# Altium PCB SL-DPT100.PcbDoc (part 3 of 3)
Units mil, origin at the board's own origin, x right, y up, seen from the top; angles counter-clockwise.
Board outline 2881.89 x 2169.29 mil, 4 copper layers (Top Layer, VCC, GND, Bottom Layer); 176 components, 168 nets, 589 pads, 369 vias.
Unrouted connection lines stored in the file: 2.
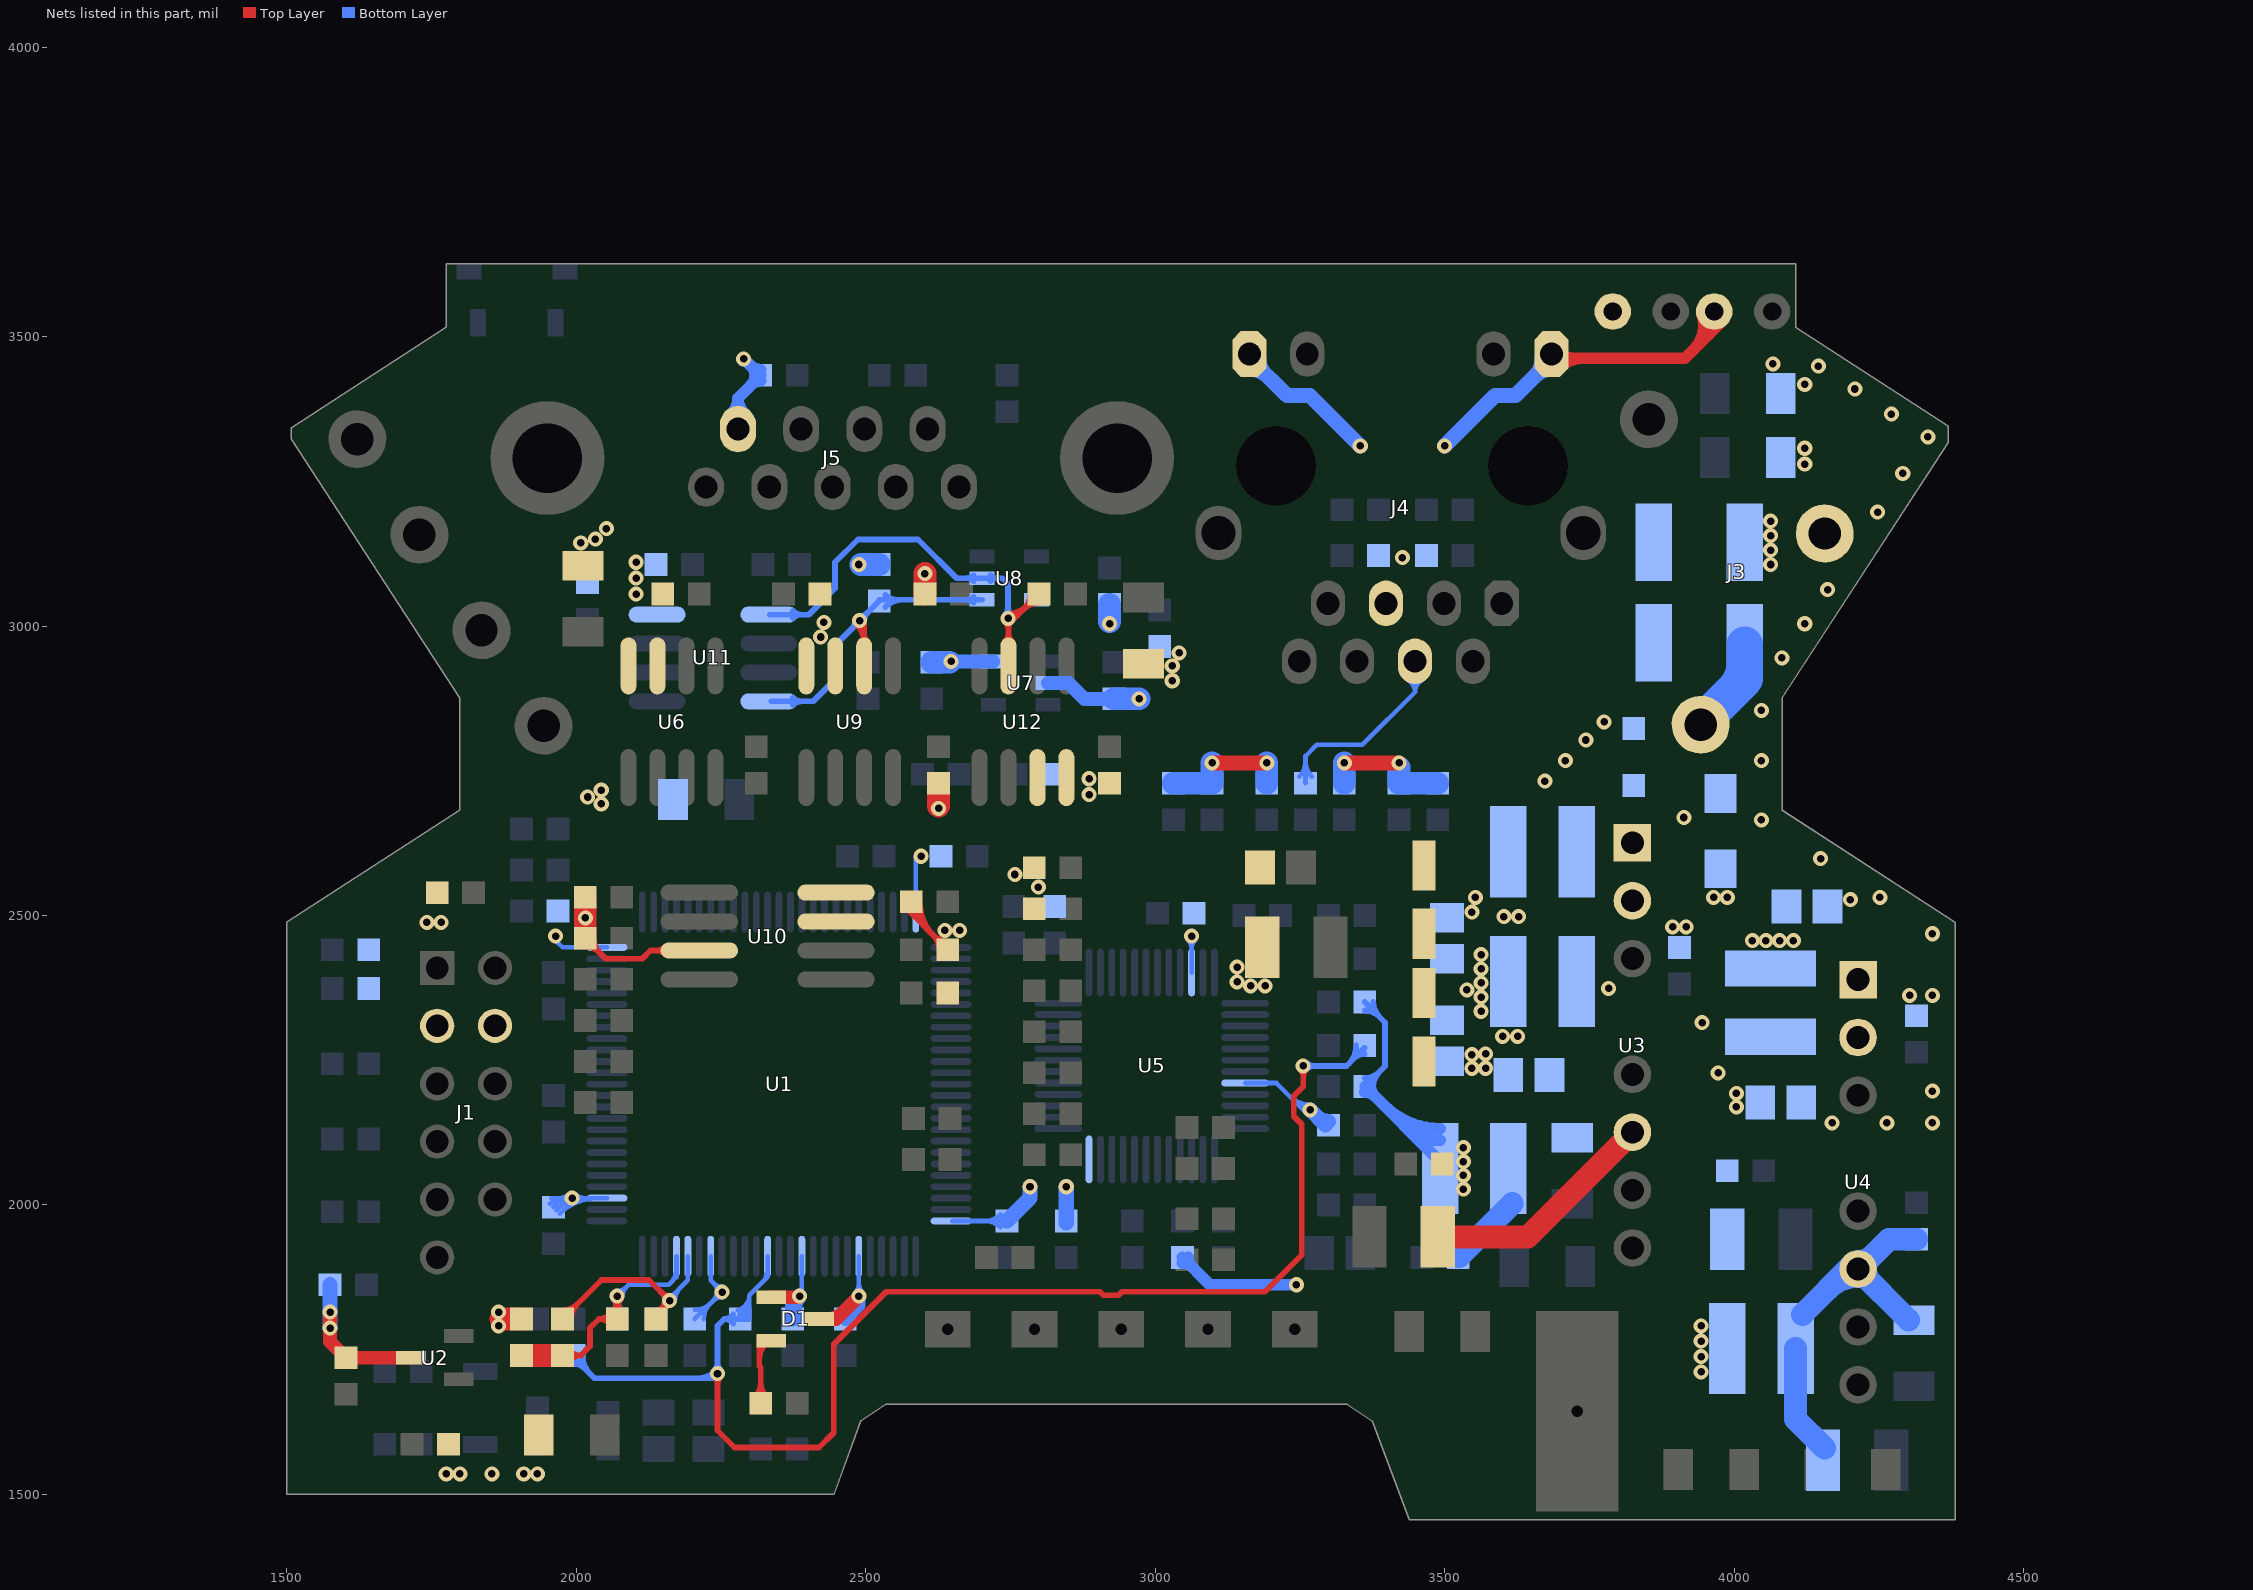
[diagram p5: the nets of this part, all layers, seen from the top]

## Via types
v1: diameter 26, hole 13, Top Layer to Bottom Layer, tented both sides, 363 vias
v2: diameter 26, hole 13, Top Layer to Bottom Layer, 4 vias
v3: diameter 27.56, hole 27.56, Top Layer to Bottom Layer, tented both sides, 2 vias

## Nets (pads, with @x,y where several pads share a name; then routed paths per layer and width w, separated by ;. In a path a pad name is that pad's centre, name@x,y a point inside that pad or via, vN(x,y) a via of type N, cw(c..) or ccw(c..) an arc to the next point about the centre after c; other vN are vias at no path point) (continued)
RST#: C48.1 R36.2 R46.1 R47.2 U1.14 | length 2981.2
  Top Layer w10: v1@2238.44,1703 cw(c2224.78,1689.35) 2244.09,1689.35 cw(c2263.41,1689.35) v1@2249.75,1703 ; v1(2244.09,1708.66) 2244.09,1610.63 2273.51,1581.21 2419.41,1581.21 2444.88,1606.69 2444.88,1759.45 2535.54,1850.11 2904.81,1850.11 2910.72,1844.2 2936.72,1844.2 2942.63,1850.11 3189.7,1850.11 3253.11,1913.52 3253.11,2139.6 3239.33,2153.38 3239.33,2188.15 3255.91,2204.72 v1@3255.91,2236.22 ; v1@3250.25,2234.5 cw(c3236.59,2220.84) 3255.91,2220.84 cw(c3275.22,2220.84) v1@3261.56,2234.5
  Bottom Layer w8: C48.1@2279.33,1818.28 ccw(c2272.2,1844.33) 2299.21,1844.33 ; C48.1@2281.44,1810.56 ccw(c2275.07,1833.85) 2299.21,1833.85 ; C48.1@2283.55,1802.85 ccw(c2277.94,1823.37) 2299.21,1823.37 ; C48.1@2299.21,1803.15 2299.21,1844.33 ; 2323.17,1868.29 ccw(c2309.57,1881.89) U1.14@2328.8,1881.89 ; U1.14@2330.71,1911.42 2330.71,1875.83 2299.21,1844.33
  Bottom Layer w10: R46.1@1933.07,1740.16 1937.01,1736.22 1996.06,1736.22 2031.49,1700.79 2242.13,1700.79 2244.09,1702.76 v1(2244.09,1708.66) 2244.09,1791.34 2255.91,1803.15 ; R46.1@1936.38,1743.47 ccw(c1953.89,1760.97) 1953.89,1736.22 ; R46.1@1943.45,1729.77 cw(c1959.02,1714.21) 1959.02,1736.22 ; R46.1@1943.45,1750.54 ccw(c1978.03,1785.12) R47.2@1978.03,1736.22 ; R46.1@1951.11,1736.22 ccw(c1951.11,1785.11) R47.2@1985.68,1750.54 ; 1970.11,1736.22 cw(c1970.11,1714.21) R47.2@1985.68,1729.77 ; 1975.25,1736.22 ccw(c1975.25,1760.97) R47.2@1992.75,1743.47 ; R47.2@1996.06,1725.47 cw(c1996.06,1699.54) 2014.4,1717.88 ; R47.2@2010.75,1740.16 ccw(c2055.72,1740.16) 2023.92,1708.36 ; 2209.71,1700.79 ccw(c2209.71,1746.98) v1@2242.37,1714.32 ; 2229.91,1700.79 ccw(c2229.91,1722.84) v1@2245.51,1707.25 ; v1@2238.44,1714.32 ccw(c2224.78,1727.98) 2244.09,1727.98 ccw(c2263.41,1727.98) v1@2249.75,1714.32 ; C48.1@2271.28,1794.96 ccw(c2255.91,1784.63) 2255.91,1803.15 ; C48.1@2271.28,1811.34 cw(c2255.91,1821.66) 2255.91,1803.15 ; C48.1@2298.03,1803.15 2255.91,1803.15 ; v1@3259.84,2240.16 3330.71,2240.16 R36.2@3362.2,2271.65 ; v1@3261.56,2234.5 cw(c3275.22,2220.84) 3275.22,2240.16 cw(c3275.22,2259.47) v1@3261.56,2245.81 ; 3334.35,2243.8 ccw(c3302.56,2275.59) R36.2@3347.52,2275.59 ; 3343.86,2253.31 cw(c3362.2,2234.96) R36.2@3362.2,2260.91
  other v1: 3255.8,2240.27
RXD: R66.1 U8.2 U11.1 U12.3 | length 1026.3
  Top Layer w10: v1@2740.41,3007.73 cw(c2725.32,2992.65) 2746.65,2992.65 ; U12.3@2740.45,2972.74 ccw(c2725.46,2987.73) 2746.65,2987.73 ccw(c2767.85,2987.73) U12.3@2752.86,2972.74 ; v1@2746.06,3011.39 ccw(c2746.06,3034.12) 2762.14,3018.04 ; v1@2746.06,3021.39 ccw(c2746.06,3068.26) 2779.21,3035.12 ; U12.3@2746.65,2923.23 2746.65,3002.56 R66.1@2799.21,3055.12 ; 2746.65,2995.5 cw(c2763.95,2995.5) v1@2751.72,3007.73 ; R66.1@2784.53,3055.12 cw(c2749.08,3055.12) 2774.14,3030.05 cw(c2799.21,3004.98) R66.1@2799.21,3040.43
  Bottom Layer w10: U11.1@2334.65,3019.68 2401.57,3019.68 2447.13,3065.24 2447.13,3110.14 2486.6,3149.61 2590.55,3149.61 2657.48,3082.68 2736.22,3082.68 2746.06,3072.83 v1@2746.06,3012.8 ; U11.1@2374.32,3013.67 cw(c2388.83,2999.16) 2388.83,3019.68 ; U11.1@2374.32,3026.09 ccw(c2389.78,3041.55) 2389.78,3019.68 ; U8.2@2686.13,3077.86 ccw(c2674.5,3066.23) 2674.5,3082.68 ccw(c2674.5,3099.12) U8.2@2686.13,3087.49 ; U8.2@2715.45,3077.86 cw(c2727.07,3066.23) 2727.07,3082.68 cw(c2727.07,3099.12) U8.2@2715.45,3087.49 ; v1@2740.41,3019.04 ccw(c2726.75,3032.7) 2746.06,3032.7 ccw(c2765.38,3032.7) v1@2751.72,3019.04
  other v1: 2746.06,3013.39
TXD: R61.1 U8.1 U9.6 U11.4 | length 809.1
  Top Layer w10: v1@2483.91,3003.6 cw(c2451.24,2970.93) U9.6@2497.44,2970.93 ; v1@2490.98,3010.67 cw(c2475.39,2995.07) 2497.44,2995.07 ; U9.6@2491.43,2972.94 ccw(c2478.42,2986.81) 2497.44,2986.81 ccw(c2516.46,2986.81) U9.6@2503.45,2972.94 ; U9.6@2497.44,2931.1 v1@2497.44,3009.65
  Bottom Layer w10: U11.4@2336.81,2870.08 2409.45,2870.08 2449.89,2910.52 2449.89,2969.57 R61.1@2523.62,3043.31 ; U11.4@2374.32,2863.67 cw(c2389.78,2848.21) 2389.78,2870.08 ; U11.4@2374.32,2876.09 ccw(c2388.83,2890.6) 2388.83,2870.08 ; v1@2481.57,3009.25 cw(c2462.25,3009.25) 2475.91,2995.6 cw(c2489.57,2981.94) v1@2489.57,3001.25 ; v1@2489.57,3017.25 ccw(c2489.57,3036.57) 2503.22,3022.91 ccw(c2516.88,3009.25) v1@2497.57,3009.25 ; R61.1@2523.62,3045.28 U8.1@2700.79,3045.28 ; R61.1@2534.01,3032.92 cw(c2563.83,3003.1) 2563.83,3045.28 ; R61.1@2534.01,3053.69 ccw(c2554.32,3074.01) 2554.32,3045.28 ; U8.1@2686.13,3040.46 ccw(c2674.5,3028.83) 2674.5,3045.28 ccw(c2674.5,3061.72) U8.1@2686.13,3050.09
  other v1: 2489.57,3009.25
V3.3: C4.1 C8.2 C27.1 C28.1 C29.1 C31.2 C32.2 C33.2 C42.1 C43.1 C44.1 C45.1 C46.1 C47.1 C55.1 C56.1 C57.2 C60.1 C64.1 C71.1 C72.1 C73.2 C74.2 C75.2 D1.1 D2.1 J1.3 J1.4 J4.4 J4.5 J4.9 J4.12 L1.2 L4.2 R15.2 R19.1 R20.2 R22.1 R23.2 R24.2 R26.1 R29.1 R31.2 R33.1 R34.2 R38.2 R48.1 R54.1 R56.2 R57.2 R58.2 R59.2 R65.2 U1.11 U1.19 U1.28 U1.50 U1.75 U1.100 U2.3 U5.22 U5.32 U5.48 U10.3 U10.7 U10.8 U12.7 U12.8 | length 5692.4
  Top Layer w10: R56.2@2015.75,2445.94 cw(c2015.75,2410.49) 2040.82,2435.56 cw(c2065.89,2460.63) R56.2@2030.43,2460.63 ; R56.2@2015.75,2460.63 2051.18,2425.2 2114.17,2425.2 2128.54,2439.57 U10.3@2212.6,2439.57 ; U10.3@2153.24,2433.36 ccw(c2138.25,2418.37) 2138.25,2439.57 ccw(c2138.25,2460.76) U10.3@2153.24,2445.77 ; C60.1@2566.93,2515.75 R58.2@2641.73,2440.94 ; C60.1@2573.43,2523.62 ccw(c2608.12,2523.62) 2583.59,2499.09 ; C60.1@2583.43,2523.62 ccw(c2642.26,2523.62) 2600.66,2482.02 ; C60.1@2593.43,2523.62 ccw(c2676.4,2523.62) 2617.73,2464.95 ; R58.2@2627.05,2440.94 ccw(c2591.59,2440.94) 2616.66,2466.01 ccw(c2641.73,2491.08) R58.2@2641.73,2455.63
  Top Layer w20: J4.9@3684.06,3462.44 3915.2,3462.44 D2.1@3982.28,3529.53 ; J4.9@3698.27,3446.23 cw(c3737.41,3407.09) 3737.41,3462.44 ; J4.9@3698.27,3473.84 ccw(c3725.79,3501.37) 3725.79,3462.44 ; 3930.36,3477.6 ccw(c3888.29,3519.66) D2.1@3945.19,3537.03 ; 3953.9,3501.15 ccw(c3924.38,3530.68) D2.1@3964.32,3542.87
  Top Layer w23.62: v1(1574.8,1814.96) 1574.8,1763.78 C55.1@1602.36,1736.22 U2.3@1714.57,1736.22 ; D1.1@2336.61,1840.55 v1@2383.86,1840.55
  Top Layer w26: v1(3098.43,2763.78) v1(3192.91,2763.78) ; v1(3326.77,2763.78) v1(3421.26,2763.78)
  Top Layer w39.37: v1@1870.08,1803.15 L1.2@1905.51,1803.15 ; R56.2@2015.75,2460.63 R59.2@2015.75,2531.5 ; v1@2625.98,2688.98 R54.1@2625.98,2728.35
  Bottom Layer w8: C46.1@1954.75,2002.02 cw(c1978.38,1978.39) C46.1@1978.38,2011.81 ; C46.1@1956.69,2011.81 U1.28@2053.15,2011.81 ; C46.1@1960.41,1996.36 cw(c1997.7,1959.07) v1@1997.7,2011.81 ; v1@1964.57,2456.69 1976.38,2444.88 U1.50@2053.15,2444.88 ; C46.1@1966.06,1990.71 cw(c2017.01,1939.76) 2017.01,2011.81 ; C46.1@1971.72,1985.05 cw(c2036.33,1920.45) U1.28@2036.33,2011.81 ; v1@1986.75,2005.45 ccw(c1971.38,1990.08) 1971.38,2011.81 ccw(c1971.38,2033.54) v1@1986.75,2018.17 ; v1@1999.47,2005.45 cw(c2014.84,1990.08) 2014.84,2011.81 cw(c2014.84,2033.54) v1@1999.47,2018.17 ; C44.1@2204.72,1803.15 2251.97,1850.39 2232.28,1870.08 U1.19@2232.28,1911.42 ; C44.1@2204.72,1818.83 ccw(c2204.72,1856.7) 2231.5,1829.93 ccw(c2258.28,1803.15) C44.1@2220.41,1803.15 ; 2235.26,1833.69 cw(c2251.97,1816.98) v1@2251.97,1840.61 ; 2237.16,1835.59 ccw(c2223.14,1849.61) v1@2242.97,1849.61 ; v1@2243.76,1849.61 ccw(c2222.03,1849.61) 2237.39,1864.97 ccw(c2252.76,1880.33) v1@2252.76,1858.61 ; v1@2389.76,1842.52 U1.11@2389.76,1911.42 ; U1.75@2586.61,2505.91 v1@2586.61,2602.36 ; U1.100@2649.61,1972.44 C45.1@2748.03,1972.44 ; C45.1@2733,1961.35 ccw(c2706.23,1934.57) 2706.23,1972.44 ccw(c2706.23,2010.31) C45.1@2733,1983.53 ; v1@3056.63,2458.2 cw(c3041.26,2442.84) 3062.99,2442.84 cw(c3084.72,2442.84) v1@3069.36,2458.2 ; U5.22@3062.99,2401.57 v1@3062.99,2464.17 ; U5.32@3155.51,2210.63 3209.65,2210.63 v1@3262.8,2157.48 ; 3232.19,2188.09 ccw(c3267.72,2223.61) v1@3267.72,2173.37 ; 3245.85,2174.43 ccw(c3267.72,2196.3) v1@3267.72,2165.37 ; C28.1@3248.75,2739.44 ccw(c3221.98,2766.21) 3259.84,2766.21 ccw(c3297.71,2766.21) C28.1@3270.93,2739.44 ; C28.1@3259.84,2728.35 3259.84,2775.59 3279.12,2794.87 3357.86,2794.87 3448.82,2885.83 ; J4.4@3436.37,2907.05 cw(c3424.51,2885.83) 3448.82,2885.83 ; J4.4@3440.28,2914.03 cw(c3432.13,2899.47) 3448.82,2899.47 cw(c3465.5,2899.45) J4.4@3457.37,2914.02 ; J4.4@3448.82,2933.07 3448.82,2885.83 ; J4.4@3461.27,2907.04 ccw(c3473.11,2885.83) 3448.82,2885.83
  Bottom Layer w10: R34.2@3362.2,2204.72 3397.24,2239.76 3397.24,2315.35 R22.1@3362.2,2350.39 ; R34.2@3362.2,2219.41 ccw(c3362.2,2254.86) 3387.27,2229.79 ccw(c3412.34,2204.72) R34.2@3376.89,2204.72 ; R22.1@3362.2,2335.71 cw(c3362.2,2300.26) 3387.27,2325.32 cw(c3412.34,2350.39) R22.1@3376.89,2350.39
  Bottom Layer w20: R23.2@3047.24,1899.76 cw(c3047.24,1876.38) 3063.78,1892.92 cw(c3080.31,1909.45) R23.2@3056.93,1909.45 ; R23.2@3047.24,1909.45 3094.49,1862.2 v1(3244.09,1862.2) ; R34.2@3362.2,2195.04 cw(c3362.2,2170.44) R34.2@3379.6,2187.84 ; R34.2@3362.71,2204.72 L4.2@3494.35,2073.09 ; R34.2@3371.89,2204.72 ccw(c3394.06,2204.72) R34.2@3378.38,2189.05 ; 3395.8,2171.63 ccw(c3492.13,2267.96) L4.2@3492.13,2131.73 ; 3429.94,2137.49 ccw(c3492.13,2199.67) L4.2@3492.13,2111.73
  Bottom Layer w26: v1(1574.8,1787.4) R48.1@1574.8,1862.2 ; C43.1@2374.02,1803.15 2374.02,1830.71 v1(2385.82,1842.52) ccw(c2408.03,1820.3) C43.1@2379.98,1806.16 ; C45.1@2744.09,1972.44 2783.86,2012.2 v1(2783.86,2031.5) ; C33.2@2846.46,1968.5 v1(2846.46,2031.5) ; J4.12@3162.81,3443.51 cw(c3162.81,3396.02) 3196.39,3429.6 ; J4.12@3169.29,3456.69 3227.75,3398.23 3267.12,3398.23 v1(3354.33,3311.02) ; J4.12@3179.33,3460.04 ccw(c3211.65,3460.04) 3188.8,3437.19 ; v1@3267.89,2164.37 C32.2@3294.47,2137.8 ; C32.2@3279.7,2152.56 ccw(c3299.21,2172.07) C32.2@3299.21,2144.48 ; v1(3500,3311.02) 3587.21,3398.23 3622.64,3398.23 J4.9@3688.98,3464.57 ; 3656.22,3431.81 cw(c3684.46,3403.58) J4.9@3684.46,3443.51 ; 3656.25,3431.84 ccw(c3628.06,3460.04) J4.9@3667.93,3460.04
  Bottom Layer w39.37: C29.1@3031.5,2728.35 R31.2@3098.43,2728.35 v1(3098.43,2763.78) ; R24.2@3192.91,2728.35 v1(3192.91,2763.78) ; R20.2@3326.77,2728.35 v1(3326.77,2763.78) ; v1@3421.26,2755.91 R15.2@3421.26,2728.35 C27.1@3488.19,2728.35
  other v1: 1775.59,1535.43 1799.21,1535.43 1854.33,1535.43 1909.45,1535.43 1933.07,1535.43 1866.14,1791.34 1866.14,1814.96 2251.97,1849.61 1993.11,2011.81 3532.48,2027.56 3532.48,2051.18 3532.48,2074.8 3532.48,2099.21 3267.72,2164.37 3164.96,2378.35 3190.16,2378.35 3141.73,2385.43 3141.73,2411.02 1964.57,2464.57 3062.99,2464.57 2636.81,2474.41 2662.4,2474.41 1742.13,2488.19 1766.54,2488.19 2015.75,2496.06 2798.23,2549.21 2757.87,2570.87 2595.67,2602.36 2625.98,2685.04 2043.31,2692.91 2019.68,2704.72 2885.83,2708.66 2043.31,2716.54 2885.83,2736.22 3427.17,3118.11
V3.3_1: C3.1 C6.2 L4.1 R3.1 U3.6 | length 541.1
  Top Layer w39.37: C3.1@3488.19,1944.88 3643.7,1944.88 U3.6@3824.41,2125.59
  Bottom Layer w39.37: C6.2@3525.06,1910.65 L4.1@3617.01,2002.6
V5.0: C17.1 C21.2 C58.1 C59.1 C61.2 C62.1 C63.1 C67.1 C68.1 C69.2 C70.2 D5.1 J5.6 L7.2 R53.2 R61.2 R63.2 R64.2 U6.7 U6.8 U7.2 U7.5 U8.5 U9.7 U9.8 U11.8 | length 671.1
  Top Layer w39.37: R64.2@2602.36,3055.12 v1(2602.36,3090.55)
  Bottom Layer w20: J5.6@2266.08,3365.39 ccw(c2242.92,3393.58) 2279.41,3393.58 ; J5.6@2279.41,3340.16 2279.41,3393.58 ; v1(2289.37,3461.61) R63.2@2314.96,3436.02 ; J5.6@2292.74,3365.39 cw(c2315.89,3393.58) 2279.41,3393.58 ; R63.2@2300.68,3450.3 ccw(c2318.9,3468.51) R63.2@2318.9,3442.76 ; R63.2@2303.06,3447.92 cw(c2288.21,3433.07) 2309.21,3433.07 cw(c2285.83,3433.07) 2302.36,3416.54 cw(c2318.9,3400) R63.2@2318.9,3423.39 ; R63.2@2318.9,3433.07 2279.41,3393.58
  Bottom Layer w23.62: v1@2648.72,2938.88 U7.5@2720.47,2938.88 ; U7.2@2814.96,2901.48 2850.49,2901.48 2877.95,2874.02 R53.2@2933.07,2874.02 ; 2909.17,2874.02 ccw(c2909.17,2894.37) R53.2@2923.57,2879.98
  Bottom Layer w39.37: v1@2492.13,3106.3 R61.2@2523.62,3106.3 ; C62.1@2614.17,2937.4 v1@2645.28,2937.4 ; v1@2921.26,3007.87 C61.2@2921.26,3037.4 ; R53.2@2929.13,2874.41 v1@2972.05,2874.41
  other v1: 3942.91,1711.61 3942.91,1738.19 3942.91,1764.76 3942.91,1791.34 2972.44,2874.02 3029.53,2905.51 3029.53,2931.1 2647.64,2938.98 3041.34,2953.74 2422.05,2981.1 2921.26,3003.94 2427.95,3006.3 2103.54,3055.12 2103.54,3082.68 2488.19,3106.3 2103.54,3110.24 2007.87,3143.7 2033.07,3150.2 2052.17,3168.31
V5.0_1: C16.1 C19.2 L7.1 R5.1 U4.6 | length 675.8
  Bottom Layer w39.37: L7.1@4106.3,1751.97 4106.3,1629.92 C16.1@4156.5,1579.72 ; L7.1@4118.11,1811.02 U4.6@4206.89,1899.8 ; 4162.09,1855 cw(c4214.17,1802.91) U4.6@4214.17,1876.57 ; U4.6@4212.6,1889.76 R5.1@4301.18,1801.18 ; U4.6@4214.17,1902.17 ccw(c4214.17,1937.81) 4239.38,1912.6 ; U4.6@4216.54,1889.76 4267.72,1940.94 C19.2@4314.96,1940.94 ; U4.6@4226.97,1889.37 ccw(c4260.71,1889.37) 4236.85,1865.51
V24+: F3.1 J3.3 | length 221.5
  Bottom Layer w62.99: J3.3@3940.94,2830.71 4018.82,2908.58 F3.1@4018.82,2967.44 ; 3999.09,2888.85 ccw(c3951.84,2936.1) F3.1@4018.66,2936.1
V24+1: D3.1 F3.2 R4.1
V24+2: D3.2 D4.2 L5.2
V24+3: C9.2 C11.1 C22.2 C65.1 C66.2 L3.1 L5.1 L6.1
  other v1: 3600.39,2291.34 3625.98,2291.34 3562.99,2334.65 3562.99,2359.05 3538.39,2371.65 3562.99,2383.46 3562.99,2407.87 3562.99,2432.28 4031.5,2456.69 4055.12,2456.69 4078.74,2456.69 4102.36,2456.69 3602.36,2498.03 3627.95,2498.03
V24+4: C10.2 L3.2 U3.2
V24+5: C23.2 L6.2 U4.2
V24-: C9.1 C10.1 C11.2 C12.2 C22.1 C23.1 C24.2 C26.1 C65.2 C66.1 D4.1 J3.1 R4.2 R71.1 U3.1 U4.1
  other v1: 4169.29,2141.73 4263.78,2141.73 4342.52,2141.73 4003.94,2169.29 4003.94,2192.91 4342.52,2196.85 3972.44,2228.35 3547.24,2236.22 3570.87,2236.22 3547.24,2259.84 3570.87,2260.83 3944.88,2314.96 4303.15,2362.2 4342.52,2362.2 3783.46,2374.02 4342.52,2468.5 3893.7,2480.32 3917.32,2480.32 3547.24,2505.91 4200.79,2527.56 3553.15,2531.5 3964.57,2531.5 3988.19,2531.5 4251.97,2531.5 4149.61,2598.43 4047.24,2665.35 3913.39,2669.29 3673.23,2732.28 3708.66,2767.72 4047.24,2767.72 3744.09,2803.15 3775.59,2834.65 4047.24,2854.33 4082.68,2944.88 4122.05,3003.94 4161.42,3062.99 4062.99,3106.3 4062.99,3131.23 4062.99,3156.17 4062.99,3181.1 4248.03,3196.85 4291.34,3263.78 4122.05,3279.53 4122.05,3307.09 4334.65,3326.77 4271.65,3366.14 4208.66,3409.45 4122.05,3417.32 4145.67,3448.82 4066.93,3452.76
V_BAT: C1.1 D1.2 | length 202.2
  Top Layer w10: C1.1@2308.51,1667.86 ccw(c2283.45,1692.93) 2318.9,1692.93 ccw(c2354.35,1692.93) C1.1@2329.28,1667.86 ; 2316.02,1732.86 cw(c2355.72,1732.86) D1.2@2327.65,1760.93 ; D1.2@2316.02,1771.65 2316.02,1721.69 2318.9,1718.82 C1.1@2318.9,1657.48
VBAT: C2.1 D1.3 U1.6 | length 311.7
  Top Layer w23.62: D1.3@2419.29,1803.15 2449.21,1803.15 v1@2488.19,1842.13 ; D1.3@2433.07,1803.15 ccw(c2433.07,1842.12) 2460.63,1814.56
  Bottom Layer w8: v1@2481.83,1848.88 ccw(c2466.46,1864.25) 2488.19,1864.25 ccw(c2509.92,1864.25) v1@2494.55,1848.88 ; v1(2488.19,1842.52) U1.6@2488.19,1911.42
  Bottom Layer w23.62: C2.1@2462.84,1810.83 ccw(c2455.71,1842.52) v1(2488.19,1842.52) 2488.19,1826.77 C2.1@2464.57,1803.15
VDDA: C40.1 C41.1 L1.1 R1.1 U1.22 | length 754.4
  Top Layer w10: R1.1@1976.38,1740.16 2007.87,1740.16 ; R1.1@1987.63,1730.72 cw(c2007.87,1713.74) 2007.87,1740.16 ; R1.1@1987.63,1749.6 ccw(c2007.87,1766.58) 2007.87,1740.16 ; C41.1@2059.62,1793.71 ccw(c2039.37,1776.72) 2039.37,1803.15 ; C41.1@2059.62,1812.59 cw(c2039.37,1829.58) 2039.37,1803.15 ; C41.1@2060.48,1813.53 ccw(c2035.41,1838.6) 2070.87,1838.6 ccw(c2106.32,1838.6) C41.1@2081.25,1813.53 ; v1@2065.21,1836.86 cw(c2051.55,1823.21) 2070.87,1823.21 cw(c2090.18,1823.21) v1@2076.52,1836.86 ; v1(2070.87,1842.52) C41.1@2070.87,1803.15 2039.37,1803.15 ; 2007.87,1740.16 2023.62,1755.91 2023.62,1787.4 2039.37,1803.15
  Top Layer w39.37: L1.1@1905.51,1740.16 R1.1@1976.38,1740.16
  Bottom Layer w8: v1(2070.87,1842.52) 2090.55,1862.2 2159.81,1862.2 2173.23,1875.63 U1.22@2173.23,1911.42 ; v1@2070.87,1851.52 ccw(c2070.87,1873.25) 2086.23,1857.88 ccw(c2101.59,1842.52) v1@2079.87,1842.52 ; 2165.55,1867.95 ccw(c2151.6,1881.89) U1.22@2171.32,1881.89
  Bottom Layer w10: C40.1@2060.48,1813.53 ccw(c2035.41,1838.6) 2070.87,1838.6 ccw(c2106.32,1838.6) C40.1@2081.25,1813.53 ; v1@2065.21,1836.86 cw(c2051.55,1823.21) 2070.87,1823.21 cw(c2090.18,1823.21) v1@2076.52,1836.86 ; C40.1@2070.87,1803.15 v1(2070.87,1842.52)
VREF+: C38.1 C39.1 R1.2 U1.21 | length 701.3
  Top Layer w10: R1.2@1976.38,1803.15 2043.59,1870.36 2125.7,1870.36 v1(2161.42,1834.65) ; R1.2@1976.38,1817.83 ccw(c1976.38,1853.29) 2001.45,1828.22 ccw(c2026.52,1803.15) R1.2@1991.06,1803.15 ; C39.1@2133.86,1807.09 v1(2161.42,1834.65) ; C39.1@2137.8,1817.83 ccw(c2137.8,1834.28) C39.1@2149.42,1822.65 ; C39.1@2142.41,1803.96 cw(c2161.54,1807.3) C39.1@2147.81,1821.04 ; C39.1@2152.26,1805.68 cw(c2184.71,1811.35) v1(2161.42,1834.65) ; v1@2161.42,1826.65 ccw(c2161.42,1807.33) 2147.76,1820.99 ccw(c2134.1,1834.65) 2153.42,1834.65 ccw(c2134.1,1834.65) 2147.76,1848.3 ccw(c2161.42,1861.96) v1@2161.42,1842.65
  Bottom Layer w8: v1@2159.45,1836.61 2192.91,1870.08 U1.21@2192.91,1911.42 ; v1@2161.42,1843.65 ccw(c2161.42,1855.87) 2170.06,1847.23 ; v1@2170.42,1834.65 cw(c2201.65,1834.65) 2179.57,1856.73
  Bottom Layer w10: C38.1@2133.86,1807.09 v1(2161.42,1834.65) ccw(c2184.71,1811.35) C38.1@2152.26,1805.68 ; C38.1@2137.8,1817.83 ccw(c2137.8,1834.28) C38.1@2149.42,1822.65 ; C38.1@2142.41,1803.96 cw(c2161.54,1807.3) C38.1@2147.81,1821.04 ; v1@2153.42,1834.65 cw(c2134.1,1834.65) 2147.76,1820.99 cw(c2161.42,1807.33) v1@2161.42,1826.65
pads on no net: J4.7 SW2.3 SW2.4 Temp1.1 Temp1.2 Temp1.3 Temp1.4 Temp1.5 Temp2.1 Temp2.2 Temp2.3 Temp2.4 U3.5 U5.8 U5.9 U5.10 U5.11 U5.12 U6.1 U6.4 U9.1 U9.4
copper on no net:
  other v3: 1864.17,3574.8 1931.1,3574.8

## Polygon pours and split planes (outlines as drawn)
V24- on Bottom Layer "V24" (solid, remove dead copper, pour order 1003): 4358.27,2129.92 4019.68,2129.92 3960.63,2188.98 3960.63,2279.53 3877.95,2362.2 3771.65,2362.2 3633.86,2224.41 3523.62,2224.41 3503.94,2244.09 3503.94,2496.06 3618.11,2610.24 3618.11,2696.85 3870.08,2948.82 3870.08,3244.09 4031.5,3244.09 4035.43,3248.03 4035.43,3464.57 4145.67,3464.57 4346.46,3334.65 4346.46,3318.9 4307.09,3263.78 4059.06,2881.89 4059.06,2673.23 4358.27,2476.38
GNDD on Bottom Layer "GNDD" (solid, remove dead copper, pour order 1004): 3004.92,2851.38 2050.2,2851.38 1948.82,2952.76 1948.82,3102.36 2027.56,3181.1 2248.03,3181.1 2283.46,3216.54 2283.46,3263.78 2248.03,3299.21 2224.41,3299.21 2192.91,3330.71 2192.91,3464.57 2241.14,3512.8 2687.01,3512.8 2795.28,3404.53 2795.28,3224.41 2870.08,3149.61 2976.38,3149.61 3064.96,3061.02 3064.96,2911.42
GNDD on Bottom Layer "GNDD" (solid, remove dead copper, pour order 1006): 4362.2,1476.38 4362.2,2086.61 3960.63,2086.61 3960.63,1874.02 3838.58,1751.97 3838.58,1476.38
GND on Bottom Layer "GND" (solid, remove dead copper, pour order 1001): 1523.62,1523.62 1523.62,2476.38 1830.71,2677.17 1925.2,2677.17 2059.06,2811.02 3023.62,2811.02 3106.3,2893.7 3106.3,3059.06 3314.96,3267.72 3314.96,3314.96 3326.77,3326.77 3527.56,3326.77 3539.37,3314.96 3539.37,3259.84 3759.84,3039.37 3759.84,2970.24 3527.72,2738.12 3527.7,2662.55 3401.57,2536.42 3401.57,2204.72 3488.19,2118.11 3807.09,2118.11 3858.27,2066.93 3858.27,1917.32 3799.21,1858.27 3488.19,1858.27 3464.57,1834.65 3464.57,1746.06 3370.08,1746.06 3370.08,1830.71 3330.71,1870.08 2500,1870.08 2500,1712.6 2429.13,1523.62
GNDD on Top Layer "GNDD" (solid, remove dead copper, pour order 1002): 3004.92,2851.38 2050.2,2851.38 1948.82,2952.76 1948.82,3102.36 2027.56,3181.1 2248.03,3181.1 2283.46,3216.54 2283.46,3263.78 2248.03,3299.21 2224.41,3299.21 2192.91,3330.71 2192.91,3464.57 2241.14,3512.8 2687.01,3512.8 2795.28,3404.53 2795.28,3224.41 2870.08,3149.61 2976.38,3149.61 3064.96,3061.02 3064.96,2911.42
GNDD on Top Layer "GNDD" (solid, remove dead copper, pour order 1007): 4362.2,1476.38 4362.2,2086.61 3960.63,2086.61 3960.63,1874.02 3838.58,1751.97 3838.58,1476.38
V24- on Top Layer "V24" (solid, remove dead copper, pour order 1005): 4358.27,2129.92 4019.68,2129.92 3960.63,2188.98 3960.63,2279.53 3877.95,2362.2 3771.65,2362.2 3633.86,2224.41 3503.94,2224.41 3484.25,2204.72 3444.88,2204.72 3444.88,2629.92 3551.18,2629.92 3618.11,2696.85 3870.08,2948.82 3870.08,3244.09 4031.5,3244.09 4035.43,3248.03 4035.43,3464.57 4145.67,3464.57 4346.46,3334.65 4346.46,3318.9 4307.09,3263.78 4059.06,2881.89 4059.06,2673.23 4358.27,2476.38
GND on Top Layer "GND" (solid, remove dead copper, pour order 1000): 1523.62,1523.62 1523.62,2476.38 1801.9,2657.48 1905.51,2657.48 2059.06,2811.02 3023.62,2811.02 3106.3,2893.7 3106.3,3059.06 3314.96,3267.72 3314.96,3314.96 3326.77,3326.77 3527.56,3326.77 3539.37,3314.96 3539.37,3259.84 3759.84,3039.37 3759.84,2970.47 3521.65,2732.28 3389.76,2732.28 3330.71,2673.23 3330.71,2169.29 3397.64,2102.36 3822.83,2102.36 3858.27,2066.93 3858.27,1917.32 3799.21,1858.27 3488.19,1858.27 3464.57,1834.65 3464.57,1746.06 3370.08,1746.06 3370.08,1830.71 3330.71,1870.08 2500,1870.08 2500,1712.6 2429.13,1523.62
V3.3 on VCC (split plane): 3539.43,3314.9 3539,3260.22 3769.59,3029.62 3769.59,2990.48 3523.41,2744.3 3520.95,2741.3 3519.13,2737.88 3518,2734.17 3517.82,2732.28 3389.76,2732.28 3330.71,2673.23 3330.71,2169.29 3397.64,2102.36 3452.76,2102.36 3469.45,2119.09 3495.1,2119.09 3496.06,2119 3827.44,2119 3885.73,2060.7 3885.73,1931.42 3808.64,1854.33 3488.19,1854.33 3488.19,1736.22 3342.52,1736.22 3342.52,1795.28 3303.15,1834.65 2566.93,1834.65 2519.68,1787.4 2519.68,1669.71 2480.39,1643.49 2480.05,1643.21 2479.67,1642.99 2478.53,1641.96 2477.34,1640.99 2477.06,1640.65 2476.74,1640.36 2475.81,1639.13 2474.84,1637.95 2474.63,1637.56 2474.37,1637.21 2473.7,1635.83 2472.98,1634.47 2472.85,1634.05 2472.66,1633.66 2431.22,1520.1 1520.1,1520.1 1520.1,2477.27 1809.58,2665.12 1809.67,2665.19 1809.77,2665.24 1811.21,2666.42 1812.66,2667.58 1812.73,2667.66 1812.82,2667.74 1814,2669.17 1815.2,2670.59 1815.26,2670.69 1815.33,2670.77 1816.21,2672.41 1817.11,2674.04 1817.14,2674.15 1817.19,2674.24 1817.74,2676.02 1818.3,2677.79 1818.31,2677.9 1818.34,2678.01 1818.53,2679.86 1818.66,2681.01 1917.32,2681.01 1921.18,2681.39 1924.89,2682.51 1928.31,2684.34 1931.31,2686.8 2056.42,2811.91 3012.8,2811.91 3016.65,2812.29 3020.36,2813.42 3023.78,2815.25 3026.78,2817.71 3098.63,2889.56 3101.09,2892.55 3102.92,2895.97 3104.05,2899.68 3104.43,2903.54 3104.23,2905.54 3104.23,3056.98 3314.96,3267.72 3314.96,3314.96 3346.46,3346.46 3507.87,3346.46
V5.0 on VCC (split plane): 3925.2,3527.56 3768.9,3371.26 3768.9,3363.17 3768.8,3362.2 3768.8,3343.7 3769.18,3339.84 3770.31,3336.13 3772.14,3332.71 3774.6,3329.71 3828.64,3275.66 3828.64,2965.87 3582.47,2719.7 3580.01,2716.7 3578.18,2713.28 3577.06,2709.57 3576.68,2705.71 3576.68,2629.85 3467.31,2520.48 3464.85,2517.49 3463.02,2514.07 3461.9,2510.35 3461.52,2506.5 3461.52,2235.24 3461.9,2231.38 3463.02,2227.67 3464.85,2224.25 3467.31,2221.25 3504.71,2183.85 3507.71,2181.39 3511.13,2179.56 3514.84,2178.43 3518.7,2178.05 3683.07,2178.05 3686.93,2178.43 3690.64,2179.56 3694.06,2181.39 3697.06,2183.85 3799.53,2286.32 3851.06,2286.32 3885.73,2251.65 3885.73,2213.58 3886.11,2209.72 3887.24,2206.01 3889.07,2202.59 3891.53,2199.6 3998.81,2092.31 4001.81,2089.85 4005.23,2088.02 4008.94,2086.9 4012.8,2086.52 4361.77,2086.52 4361.74,1714.49 4361.79,1476.79 3964.57,1476.79 3964.57,1586.61 3937.01,1586.61 3838.58,1685.04 3838.58,1828.33 3919.5,1909.24 3921.96,1912.24 3923.79,1915.66 3924.91,1919.37 3925.29,1923.23 3925.29,2068.9 3924.91,2072.76 3923.79,2076.47 3921.96,2079.89 3919.5,2082.88 3849.62,2152.77 3846.62,2155.23 3843.2,2157.05 3839.49,2158.18 3835.63,2158.56 3504.26,2158.56 3442.02,2220.79 3442.02,2522.71 3551.39,2632.08 3553.85,2635.07 3555.68,2638.49 3556.8,2642.2 3557.18,2646.06 3557.18,2722.12 3803.36,2968.3 3805.82,2971.29 3807.64,2974.71 3808.77,2978.42 3809.15,2982.28 3809.15,3259.45 3808.77,3263.31 3807.64,3267.02 3805.82,3270.44 3803.36,3273.44 3749.77,3327.02 3750.1,3330.32 3750.1,3476.77 3749.72,3480.63 3748.59,3484.34 3746.76,3487.76 3744.3,3490.76 3685.64,3549.42 3682.64,3551.88 3679.22,3553.71 3675.51,3554.83 3671.65,3555.21 2889.76,3555.21 2885.9,3554.83 2882.19,3553.71 2878.77,3551.88 2875.78,3549.42 2800.97,3474.62 2798.51,3471.62 2796.69,3468.2 2795.72,3465.01 2795.28,3464.57 2795.28,3461.6 2795.18,3460.63 2795.18,3232.28 2795.28,3231.32 2795.28,3224.41 2799.08,3220.6 2800.97,3218.3 2863.97,3155.3 2866.27,3153.41 2870.08,3149.61 2876.99,3149.61 2877.95,3149.51 2976.06,3149.51 3064.67,3060.9 3064.67,2911.54 3004.6,2851.47 2050.1,2851.47 1948.82,2952.76 1948.82,3102.36 2027.56,3181.1 2248.03,3181.1 2283.46,3216.54 2283.46,3263.78 2248.03,3299.21 2224.41,3299.21 2192.91,3330.71 2192.91,3472.44 2240.16,3519.68 2767.72,3519.68 2834.65,3586.61 3925.2,3586.61
V24+3 on VCC (split plane): 4142.62,3468.5 4349.98,3334.15 4349.98,3322.76 4065.95,2886.88 4065.09,2885.22 4064.21,2883.56 4064.18,2883.47 4064.14,2883.39 4063.61,2881.58 4063.07,2879.78 4063.06,2879.69 4063.04,2879.6 4062.87,2877.73 4062.7,2875.86 4063.15,2681.93 4063.16,2681.82 4063.15,2681.71 4063.36,2679.86 4063.55,2678.01 4063.58,2677.91 4063.59,2677.79 4064.16,2676.01 4064.7,2674.24 4064.75,2674.15 4064.78,2674.04 4065.69,2672.41 4066.56,2670.77 4066.63,2670.69 4066.69,2670.59 4067.88,2669.17 4069.07,2667.74 4069.16,2667.66 4069.23,2667.58 4070.68,2666.42 4072.12,2665.24 4072.22,2665.19 4072.31,2665.12 4361.79,2477.27 4361.77,2126.08 4020.99,2126.08 3925.29,2221.78 3925.29,2259.84 3924.91,2263.7 3923.79,2267.41 3921.96,2270.83 3919.5,2273.83 3873.24,2320.09 3870.24,2322.55 3866.82,2324.38 3863.11,2325.5 3859.25,2325.88 3791.34,2325.88 3787.48,2325.5 3783.77,2324.38 3780.35,2322.55 3777.35,2320.09 3674.88,2217.61 3526.89,2217.61 3501.08,2243.43 3501.08,2498.3 3610.44,2607.67 3612.9,2610.66 3614.73,2614.08 3615.86,2617.79 3616.24,2621.65 3616.24,2697.52 3862.41,2943.69 3864.87,2946.69 3866.7,2950.11 3867.83,2953.82 3868.21,2957.68 3868.21,3248.03 4027.56,3248.03 4027.56,3468.5
GND on GND (split plane): 3539.43,3314.9 3539,3260.22 3769.59,3029.62 3769.59,2990.48 3523.41,2744.3 3520.95,2741.3 3519.13,2737.88 3518,2734.17 3517.62,2730.31 3517.62,2654.26 3408.26,2544.89 3405.8,2541.89 3403.97,2538.47 3402.84,2534.76 3402.46,2530.91 3402.46,2212.6 3402.84,2208.74 3403.97,2205.03 3405.8,2201.61 3408.26,2198.61 3482.08,2124.79 3485.07,2122.33 3488.49,2120.5 3492.2,2119.38 3496.06,2119 3827.44,2119 3885.73,2060.7 3885.73,1931.42 3808.64,1854.33 3488.19,1854.33 3488.19,1736.22 3342.52,1736.22 3342.52,1795.28 3303.15,1834.65 2566.93,1834.65 2519.68,1787.4 2519.68,1669.71 2480.39,1643.49 2480.05,1643.21 2479.67,1642.99 2478.53,1641.96 2477.34,1640.99 2477.06,1640.65 2476.74,1640.36 2475.81,1639.13 2474.84,1637.95 2474.63,1637.56 2474.37,1637.21 2473.7,1635.83 2472.98,1634.47 2472.85,1634.05 2472.66,1633.66 2431.22,1520.1 1520.1,1520.1 1520.1,2477.27 1809.58,2665.12 1809.67,2665.19 1809.77,2665.24 1811.21,2666.42 1812.66,2667.58 1812.73,2667.66 1812.82,2667.74 1814,2669.17 1815.2,2670.59 1815.26,2670.69 1815.33,2670.77 1816.21,2672.41 1817.11,2674.04 1817.14,2674.15 1817.19,2674.24 1817.74,2676.02 1818.3,2677.79 1818.31,2677.9 1818.34,2678.01 1818.53,2679.86 1818.66,2681.01 1917.32,2681.01 1921.18,2681.39 1924.89,2682.51 1928.31,2684.34 1931.31,2686.8 2056.42,2811.91 3012.8,2811.91 3016.65,2812.29 3020.36,2813.42 3023.78,2815.25 3026.78,2817.71 3098.63,2889.56 3101.09,2892.55 3102.92,2895.97 3104.05,2899.68 3104.43,2903.54 3104.23,2905.54 3104.23,3056.98 3314.96,3267.72 3314.96,3314.96 3346.46,3346.46 3507.87,3346.46
GNDD on GND (split plane): 3925.2,3527.56 3768.9,3371.26 3768.9,3363.17 3768.8,3362.2 3768.8,3343.7 3769.18,3339.84 3770.31,3336.13 3772.14,3332.71 3774.6,3329.71 3828.64,3275.66 3828.64,2965.87 3582.47,2719.7 3580.01,2716.7 3578.18,2713.28 3577.06,2709.57 3576.68,2705.71 3576.68,2629.85 3467.31,2520.48 3464.85,2517.49 3463.02,2514.07 3461.9,2510.35 3461.52,2506.5 3461.52,2235.24 3461.9,2231.38 3463.02,2227.67 3464.85,2224.25 3467.31,2221.25 3504.71,2183.85 3507.71,2181.39 3511.13,2179.56 3514.84,2178.43 3518.7,2178.05 3683.07,2178.05 3686.93,2178.43 3690.64,2179.56 3694.06,2181.39 3697.06,2183.85 3799.53,2286.32 3851.06,2286.32 3885.73,2251.65 3885.73,2213.58 3886.11,2209.72 3887.24,2206.01 3889.07,2202.59 3891.53,2199.6 3998.81,2092.31 4001.81,2089.85 4005.23,2088.02 4008.94,2086.9 4012.8,2086.52 4361.77,2086.52 4361.74,1714.49 4361.79,1476.79 3964.57,1476.79 3964.57,1586.61 3937.01,1586.61 3838.58,1685.04 3838.58,1828.33 3919.5,1909.24 3921.96,1912.24 3923.79,1915.66 3924.91,1919.37 3925.29,1923.23 3925.29,2068.9 3924.91,2072.76 3923.79,2076.47 3921.96,2079.89 3919.5,2082.88 3849.62,2152.77 3846.62,2155.23 3843.2,2157.05 3839.49,2158.18 3835.63,2158.56 3504.26,2158.56 3442.02,2220.79 3442.02,2522.71 3551.39,2632.08 3553.85,2635.07 3555.68,2638.49 3556.8,2642.2 3557.18,2646.06 3557.18,2722.12 3803.36,2968.3 3805.82,2971.29 3807.64,2974.71 3808.77,2978.42 3809.15,2982.28 3809.15,3259.45 3808.77,3263.31 3807.64,3267.02 3805.82,3270.44 3803.36,3273.44 3749.77,3327.02 3750.1,3330.32 3750.1,3476.77 3749.72,3480.63 3748.59,3484.34 3746.76,3487.76 3744.3,3490.76 3685.64,3549.42 3682.64,3551.88 3679.22,3553.71 3675.51,3554.83 3671.65,3555.21 2889.76,3555.21 2885.9,3554.83 2882.19,3553.71 2878.77,3551.88 2875.78,3549.42 2800.97,3474.62 2798.51,3471.62 2796.69,3468.2 2795.72,3465.01 2795.28,3464.57 2795.28,3461.6 2795.18,3460.63 2795.18,3232.28 2795.28,3231.32 2795.28,3224.41 2799.08,3220.6 2800.97,3218.3 2863.97,3155.3 2866.27,3153.41 2870.08,3149.61 2876.99,3149.61 2877.95,3149.51 2976.06,3149.51 3064.67,3060.9 3064.67,2942.62 3047.24,2925.2 3047.24,2894.12 3004.6,2851.47 2050.1,2851.47 1948.82,2952.76 1948.82,3102.36 2027.56,3181.1 2248.03,3181.1 2283.46,3216.54 2283.46,3263.78 2248.03,3299.21 2224.41,3299.21 2192.91,3330.71 2192.91,3472.44 2240.16,3519.68 2767.72,3519.68 2834.65,3586.61 3925.2,3586.61
V24- on GND (split plane): 4142.62,3468.5 4349.98,3334.15 4349.98,3322.76 4065.95,2886.88 4065.09,2885.22 4064.21,2883.56 4064.18,2883.47 4064.14,2883.39 4063.61,2881.58 4063.07,2879.78 4063.06,2879.69 4063.04,2879.6 4062.87,2877.73 4062.7,2875.86 4063.15,2681.93 4063.16,2681.82 4063.15,2681.71 4063.36,2679.86 4063.55,2678.01 4063.58,2677.91 4063.59,2677.79 4064.16,2676.01 4064.7,2674.24 4064.75,2674.15 4064.78,2674.04 4065.69,2672.41 4066.56,2670.77 4066.63,2670.69 4066.69,2670.59 4067.88,2669.17 4069.07,2667.74 4069.16,2667.66 4069.23,2667.58 4070.68,2666.42 4072.12,2665.24 4072.22,2665.19 4072.31,2665.12 4361.79,2477.27 4361.77,2126.08 4020.99,2126.08 3925.29,2221.78 3925.29,2259.84 3924.91,2263.7 3923.79,2267.41 3921.96,2270.83 3919.5,2273.83 3873.24,2320.09 3870.24,2322.55 3866.82,2324.38 3863.11,2325.5 3859.25,2325.88 3791.34,2325.88 3787.48,2325.5 3783.77,2324.38 3780.35,2322.55 3777.35,2320.09 3674.88,2217.61 3526.89,2217.61 3501.08,2243.43 3501.08,2498.3 3610.44,2607.67 3612.9,2610.66 3614.73,2614.08 3615.86,2617.79 3616.24,2621.65 3616.24,2697.52 3862.41,2943.69 3864.87,2946.69 3866.7,2950.11 3867.83,2953.82 3868.21,2957.68 3868.21,3248.03 4027.56,3248.03 4027.56,3468.5

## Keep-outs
Keep-Out Layer:
  lines w7.87: 1500,2464.57 1500,1500 2444.88,1500 ; 1500,2466.14 cw(c1539.37,2466.14) 1519.69,2500.24 ; 1519.31,2500.58 1798.64,2681.98 ; 1775.48,3515.91 1534.46,3359.39 ccw(c1554.13,3325.32) 1520.03,3305.63 1799.1,2875.91 1799.1,2681.22 ; 1775.59,3515.91 1775.59,3625.98 4106.3,3625.98 4106.3,3515.91 ; 2445.28,1500 2491.43,1626.81 ; 2491.54,1626.77 cw(c2535.01,1608.27) 2535.01,1655.51 3331.79,1655.51 ; 3331.79,1655.6 cw(c3331.79,1608.36) 3375.26,1626.86 3438.16,1456.69 ; 3438.98,1456.69 4381.32,1456.69 4381.32,2464.57 ; 4082.68,2681.98 4362.01,2500.58 ; 4082.79,2681.22 4082.79,2875.91 4361.86,3305.63 ccw(c4327.76,3325.32) 4347.45,3359.41 4106.41,3515.91 ; 4361.64,2500.24 cw(c4341.95,2466.14) 4381.32,2466.14

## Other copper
Top Layer:
  region net V3.3: 3496.06,2090.55 3510.24,2090.55 3519.68,2100 3545.28,2100 3545.28,2027.56 3519.68,2027.56 3496.06,2051.18
  region net V3.3: 3155.51,2583.66 3206.69,2583.66 3206.69,2505.91 3214.57,2498.03 3214.57,2384.65 3195.28,2365.35 3144.09,2365.35 3128.94,2380.51 3128.94,2415.35 3155.51,2441.93
  region net V3.3: 1779.53,2539.37 1779.53,2488.19 1732.68,2488.19 1732.68,2496.85 1740.16,2504.33 1740.16,2539.37
  region net V3.3: 1759.84,1606.3 1877.95,1606.3 1909.45,1637.8 1960.63,1637.8 1960.63,1566.93 1945.67,1551.97 1945.67,1534.65 1933.46,1522.44 1775.59,1522.44 1762.6,1535.43 1762.6,1564.17 1759.84,1566.93
  region net V3.3: 2811.02,2511.81 2811.02,2602.36 2771.65,2602.36 2748.03,2578.74 2748.03,2562.99 2771.65,2539.37 2771.65,2511.81
  region net V3.3: 2795.28,2787.4 2852.36,2787.4 2891.73,2748.03 2921.26,2748.03 2921.26,2725.98 2894.09,2698.82 2888.98,2698.82 2885.83,2695.67 2859.06,2695.67 2852.36,2688.98 2795.28,2688.98
  region net V3.3: 2622.05,2366.14 2622.05,2464.57 2567.32,2519.29 2583.86,2519.29 2615.75,2487.4 2662.99,2487.4 2671.26,2479.13 2671.26,2464.96 2661.42,2455.12 2661.42,2366.14
  region net V5.0: 2972.44,2960.63 3051.18,2960.63 3051.18,2945.87 3042.32,2937.01 3042.32,2904.53 3016.73,2904.53 3011.81,2909.45 2972.44,2909.45
  region net V5.0: 2047.24,3099.41 2047.24,3146.65 2059.06,3158.46 2059.06,3178.15 2044.29,3178.15 2022.64,3156.5 2009.84,3156.5 2005.91,3152.56 1999.02,3152.56 1976.38,3129.92 1976.38,3099.41
  region net V24+3: 3444.88,2322.83 3549.21,2322.83 3594.49,2277.56 3631.89,2277.56 3641.73,2287.4 3641.73,2503.94 3633.86,2511.81 3596.46,2511.81 3553.15,2468.5 3527.56,2468.5 3484.25,2511.81 3444.88,2511.81
  region net PB3: 2577.76,2421.26 2564.57,2421.26 2556.1,2412.8 2536.42,2412.8 2523.43,2425.79 2501.85,2425.79 2501.85,2438.98 2521.65,2438.98 2577.76,2438.98
  region net V3.3: 2381.89,2539.76 2381.89,2489.57 2390.16,2481.3 2512.8,2481.3 2535.43,2503.94 2578.74,2503.94 2598.43,2484.25 2598.43,2543.31 2517.72,2543.31 2511.81,2549.21 2391.34,2549.21
  region net PB8: 2558.66,2054.33 2562.99,2058.66 2562.99,2067.72 2600,2067.72 2600,2059.06 2576.38,2035.43
  region net PA4: 2065.75,2566.93 2091.73,2566.93 2091.73,2557.87 2098.43,2551.18 2098.43,2550.39 2059.06,2550.39 2059.06,2551.18 2065.75,2557.87
  region net NetR46_2: 1810.24,1803.15 1784.25,1803.15 1784.25,1798.03 1771.65,1785.43 1771.65,1784.65 1822.83,1784.65 1822.83,1785.43 1810.24,1798.03
  region net V5.0: 2169.29,3106.3 2149.61,3125.98 2098.43,3125.98 2076.54,3104.09 2076.57,2889.96 2084.65,2881.89 2146.06,2881.89 2154.13,2889.96 2154.13,3020.28 2169.29,3035.43
  region net V5.0: 2453.07,2881.89 2461.22,2890 2461.22,2972.24 2440.94,2992.52 2440.94,3074.8 2401.57,3074.8 2401.57,2990.19 2383.62,2972.24 2383.62,2889.96 2391.66,2881.89
  region net GNDE: 3905.51,1578.74 3837.4,1578.74 3799.21,1616.93 3800.19,1771.85 3845.28,1816.93 3543.31,1816.93 3543.31,1746.06 3578.74,1746.06 3665.35,1659.45 3665.35,1470.47 3800,1470.47 3837.4,1507.87 3905.51,1507.87
  pour cut-out: 3444.88,2543.31 3444.88,2511.81 3500,2511.81 3523.62,2488.19 3523.62,2543.31
  pour cut-out: 3444.88,2322.83 3549.21,2322.83 3580.71,2291.34 3444.88,2291.34
  pour cut-out: 1956.69,1832.68 1925.2,1832.68 1925.2,1759.84 1956.69,1759.84
  pour cut-out: 2118.11,1832.68 2090.55,1832.68 2090.55,1759.84 2118.11,1759.84
Bottom Layer:
  rectangle net NetR39_1: 3174.61,2165.35 3198.78,2173.74
  rectangle net PB13: 2131.5,2467.32 2139.76,2480.32
  region net NetR6_1: 2793.31,2131.89 2852.36,2131.89 2852.36,2129.92 2820.87,2098.43 2814.96,2098.43 2814.96,2106.3 2793.31,2127.95
  region net V3.3: 3433.07,2141.73 3433.07,2133.86 3460.63,2106.3 3460.63,1984.25 3523.62,1984.25 3545.28,2005.91 3545.28,2120.08 3523.62,2141.73
  region net V3.3: 2165.35,2736.22 2141.73,2736.22 2135.04,2729.53 2037.8,2729.53 2025.98,2717.72 2019.68,2717.72 2019.68,2691.73 2026.38,2691.73 2038.19,2679.92 2127.17,2679.92 2141.73,2665.35 2165.35,2665.35
  region net V3.3: 1661.42,2440.94 1661.42,2370.08 1692.59,2338.9 1858.27,2338.9 1858.27,2279.99 1696.38,2279.99 1622.05,2354.33 1622.05,2440.94
  region net V3.3: 3047.24,2503.94 3047.24,2484.25 3050.39,2481.1 3050.39,2464.57 3075.59,2464.57 3075.59,2473.23 3086.61,2484.25 3086.61,2503.94
  region net V3.3: 2846.46,2515.75 2846.46,2535.43 2830.31,2535.43 2782.28,2583.46 2757.87,2583.46 2757.87,2558.27 2770.87,2558.27 2813.39,2515.75
  region net V3.3: 2822.83,2763.78 2822.83,2724.41 2851.97,2724.41 2878.74,2697.64 2885.83,2704.72 2885.83,2749.21 2857.09,2749.21 2842.52,2763.78
  region net V3.3: 2629.92,2622.05 2590.55,2622.05 2582.68,2614.17 2582.68,2555.12 2610.24,2582.68 2629.92,2582.68
  region net V3.3: 1948.82,2511.81 1948.82,2461.81 1969.68,2440.94 2007.87,2440.94 1988.19,2460.63 1988.19,2511.81
  pour cut-out: 2826.77,3104.33 2826.77,3055.12 2653.54,3055.12 2653.54,3104.33
  pour cut-out: 2688.98,2925.2 2688.98,2877.95 2736.22,2877.95 2736.22,2925.2
  pour cut-out: 2543.31,3462.6 2566.93,3462.6 2566.93,3403.54 2543.31,3403.54
  region net V5.0: 3001.97,2984.25 3028.54,2984.25 3050.2,2962.6 3050.2,2958.66 3050.2,2944.88 3042.32,2937.01 3042.32,2904.53 3016.73,2904.53 3016.73,2934.06 3001.97,2948.82
  region net V5.0: 2795.28,3057.09 2940.94,3057.09 2940.94,3017.72 2901.57,3017.72 2885.83,3033.46 2795.28,3033.46
  region net V5.0: 2000,3076.77 2000,3147.64 2008.86,3156.5 2022.64,3156.5 2044.29,3178.15 2059.06,3178.15 2059.06,3158.46 2039.37,3138.78 2039.37,3076.77
  region net V3.3: 3468.5,3141.73 3366.14,3141.73 3366.14,3102.36 3369.33,3099.17 3369.33,3047.24 3428.35,3047.24 3428.35,3077.95 3452.76,3102.36 3468.5,3102.36
  region net V24+3: 3641.73,2574.8 3641.73,2287.4 3631.89,2277.56 3594.49,2277.56 3578.74,2293.31 3474.41,2293.31 3474.41,2450.79 3553.15,2450.79 3578.74,2476.38 3578.74,2574.8
  region net V24+3: 4116.14,2523.62 4116.14,2464.57 4141.73,2438.98 4141.73,2411.42 3984.25,2411.42 3984.25,2438.98 4068.9,2523.62
  region net V24+5: 4214.17,2256.89 4166.38,2256.93 4141.65,2232.2 4141.73,2177.17 4090.55,2177.17 4090.55,2232.28 4055.12,2267.72 4055.12,2321.85 4214.17,2321.85
  region net V24+4: 3655.51,2224.41 3655.51,2261.81 3696.85,2303.15 3696.85,2464.57 3717.48,2464.57 3802.17,2549.25 3824.21,2527.2 3824.21,2493.11 3806.85,2493.11 3759.84,2446.1 3759.84,2307.09 3706.69,2253.94 3706.69,2224.41
  region net V24+2: 3976.38,2744.09 3751.97,2744.09 3696.85,2688.98 3696.85,2625.98 3759.84,2625.98 3759.84,2688.98 3775.59,2704.72 3921.26,2704.72 3948.82,2677.17 3976.38,2677.17
  region net V24+1: 3892.68,3211.69 3829.68,3211.69 3829.68,2880.87 3807.09,2858.27 3807.09,2803.11 3846.46,2803.11 3846.46,2842.52 3892.68,2888.74
  region net GNDE: 3992.13,3437.01 3992.13,3255.91 3940.94,3255.91 3889.76,3307.09 3851.97,3307.09 3851.97,3407.09 3911.02,3407.09 3940.94,3437.01
  region net V5.0: 4019.68,1673.23 3956.69,1673.23 3930.12,1699.8 3930.12,1804.13 3958.66,1832.68 3958.66,1994.09 3968.5,2003.94 3968.5,2078.74 4007.87,2078.74 4007.87,2003.94 4017.72,1994.09 4017.72,1832.68 4019.68,1830.71
  region net V3.3: 2886,2088 2880,2088 2880,2083 2835,2038 2838.58,2023.62 2856,2023 2871,2038 2885,2038
  region net PA3: 2038,1941 2064,1941 2064,1952 2081,1969 2081,1973 2021,1973 2021,1969 2038,1952
  region net PA2: 2114,1944 2114,1899 2109,1899 2100,1908 2087,1908 2087,1934 2100,1934 2110,1944
  region net V5.0: 2157.48,3125.98 2157.48,3053.15 2185.04,3025.59 2185.04,3015.75 2090.94,3015.75 2090.55,3016.14 2090.55,3115.75 2100.79,3125.98
  region net NetR40_1: 3124.02,2354.33 3200.79,2354.33 3200.79,2346.46 3124.02,2346.46
  region net V3.3_1: 3824.02,2093.11 3824.02,2148.98 3801.85,2148.98 3794.61,2141.73 3610.24,2141.73 3610.24,2047.24 3641.73,2047.24 3685.04,2090.55 3755.91,2090.55 3758.43,2093.07
  region net GNDE: 3905.51,1578.74 3837.4,1578.74 3799.21,1616.93 3799.21,1692.91 3675.2,1816.93 3543.31,1816.93 3543.31,1746.06 3578.74,1746.06 3665.35,1659.45 3665.35,1470.47 3800,1470.47 3837.4,1507.87 3905.51,1507.87
  region net OSC_OUT: 2291.34,1681.1 2295.28,1681.1 2303.15,1673.23 2318.9,1673.23 2318.9,1708.66
  region net NetC34_2: 3137.8,2484.25 3116.39,2484.25 3137.8,2505.66
  region net V3.3: 1960.63,2015.75 2001.97,2015.75 2001.97,2002.95 1979.33,1980.32 1960.63,1980.32
VCC (plane layer: these items are gaps in the copper):
  region: 4106.3,3625.98 4106.3,3515.75 4177.17,3468.5 3925.2,3468.5 3925.2,3625.98
  region: 4027.56,3535.43 4027.56,3248.03 3866.14,3248.03 3768.9,3345.28 3768.9,3371.26 3933.07,3535.43
  region: 3795.28,3275.59 3795.28,3003.94 3539,3260.22 3539.43,3314.9 3507.87,3346.46 3346.46,3346.46 3314.96,3314.96 3314.96,3267.72 3098.43,3051.18 3074.8,3051.18 2976.38,3149.61 2870.08,3149.61 2795.28,3224.41 2795.28,3464.57 2873.95,3543.25 3673.29,3543.25 3724.47,3492.07 3724.47,3346.4
  region: 3488.19,1854.33 3488.19,1736.22 3374.02,1736.22 3374.02,1629.92 3448.82,1448.82 3964.57,1448.82 3964.57,1586.61 3937.01,1586.61 3838.58,1685.04 3838.58,1854.33
  region: 3937.01,3622.05 3937.01,3586.61 2834.65,3586.61 2767.72,3519.68 2240.16,3519.68 2192.91,3472.44 2192.91,3330.71 2224.41,3299.21 2248.03,3299.21 2283.46,3263.78 2283.46,3216.54 2248.03,3181.1 2027.56,3181.1 1948.82,3102.36 1948.82,2952.76 2057.09,2844.49 1913.39,2700.79 1799.21,2700.79 1799.21,2877.95 1500,3338.58 1775.59,3515.75 1775.59,3622.05
  region: 3374.02,1641.73 3374.02,1736.22 3342.52,1736.22 3342.52,1795.28 3303.15,1834.65 2566.93,1834.65 2519.68,1787.4 2519.68,1641.73
  region: 3519.68,2732.28 3389.76,2732.28 3330.71,2673.23 3330.71,2169.29 3397.64,2102.36 3452.76,2102.36 3469.45,2119.09 3508.11,2119.09 3405.51,2221.69 3405.51,2539.37 3519.68,2653.54
  lines w39.37: 1807.09,2700.79 1917.32,2700.79 2048.23,2831.69 3012.8,2831.69 3084.65,2903.54 ; 3078.74,3074.8 2984.25,3169.29 2877.95,3169.29 2814.96,3232.28 2814.96,3460.63 2889.76,3535.43 3671.65,3535.43 3730.32,3476.77 3730.32,3330.32 ; 3084.45,2903.54 3084.45,3527.56 ; 3730.31,3318.5 3789.37,3259.45 3789.37,2982.28 3537.4,2730.31 3537.4,2646.06 3422.24,2530.91 3422.24,2212.6 3496.06,2138.78 3835.63,2138.78 3905.51,2068.9 3905.51,1923.23 3796.26,1813.98 ; 3788.58,3362.2 3788.58,3343.7 3848.43,3283.86 3848.43,2957.68 3596.46,2705.71 3596.46,2621.65 3481.3,2506.5 3481.3,2235.24 3518.7,2197.83 3683.07,2197.83 3791.34,2306.1 3859.25,2306.1 3905.51,2259.84 3905.51,2213.58 4012.8,2106.3 4381.89,2106.3
GND (plane layer: these items are gaps in the copper):
  region: 3937.01,3622.05 3937.01,3586.61 2834.65,3586.61 2767.72,3519.68 2240.16,3519.68 2192.91,3472.44 2192.91,3330.71 2224.41,3299.21 2248.03,3299.21 2283.46,3263.78 2283.46,3216.54 2248.03,3181.1 2027.56,3181.1 1948.82,3102.36 1948.82,2952.76 2057.09,2844.49 1913.39,2700.79 1799.21,2700.79 1799.21,2877.95 1500,3338.58 1775.59,3515.75 1775.59,3622.05
  region: 3488.19,1854.33 3488.19,1736.22 3370.08,1736.22 3370.08,1633.86 3440.94,1448.82 3964.57,1448.82 3964.57,1586.61 3937.01,1586.61 3838.58,1685.04 3838.58,1854.33
  region: 3795.28,3275.59 3795.28,3003.94 3539,3260.22 3539.43,3314.9 3507.87,3346.46 3346.46,3346.46 3314.96,3314.96 3314.96,3267.72 3098.43,3051.18 3074.8,3051.18 2976.38,3149.61 2870.08,3149.61 2795.28,3224.41 2795.28,3464.57 2873.95,3543.25 3673.29,3543.25 3724.47,3492.07 3724.47,3346.4
  region: 4027.56,3535.43 4027.56,3248.03 3866.14,3248.03 3768.9,3345.28 3768.9,3371.26 3933.07,3535.43
  region: 4106.3,3625.98 4106.3,3515.75 4177.17,3468.5 3925.2,3468.5 3925.2,3625.98
  region: 3370.08,1641.73 3370.08,1736.22 3342.52,1736.22 3342.52,1795.28 3303.15,1834.65 2566.93,1834.65 2519.68,1787.4 2519.68,1641.73
  region: 3070.87,2948.82 3070.87,2913.39 3047.24,2889.76 3047.24,2925.2
  lines w39.37: 1807.09,2700.79 1917.32,2700.79 2048.23,2831.69 3012.8,2831.69 3084.65,2903.54 ; 3078.74,3074.8 2984.25,3169.29 2877.95,3169.29 2814.96,3232.28 2814.96,3460.63 2889.76,3535.43 3671.65,3535.43 3730.32,3476.77 3730.32,3330.32 ; 3084.45,2903.54 3084.45,3527.56 ; 3730.32,3318.5 3789.37,3259.45 3789.37,2982.28 3537.4,2730.31 3537.4,2646.06 3422.24,2530.91 3422.24,2212.6 3496.06,2138.78 3835.63,2138.78 3905.51,2068.9 3905.51,1923.23 3796.26,1813.98 ; 3788.58,3362.2 3788.58,3343.7 3848.43,3283.86 3848.43,2957.68 3596.46,2705.71 3596.46,2621.65 3481.3,2506.5 3481.3,2235.24 3518.7,2197.83 3683.07,2197.83 3791.34,2306.1 3859.25,2306.1 3905.51,2259.84 3905.51,2213.58 4012.8,2106.3 4381.89,2106.3

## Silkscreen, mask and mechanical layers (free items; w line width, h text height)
Top Overlay:
  text "SL-DPT100 V1.0.0" at 3114.17,2783.46 h40
  text "I" at 2055.12,2590.55 h28
  text "T" at 2149.61,2590.55 h28
  text "R" at 2244.09,2590.55 h28
  text "E" at 2346.46,2590.55 h28
Bottom Overlay:
  lines w7.87: 3783.46,2074.8 3834.65,2074.8 ; 3858.27,2047.24 3917.32,2047.24 3917.32,2106.3 3858.27,2106.3
  text "I" at 2114.17,2590.55 h28
  text "T" at 2169.29,2590.55 h28
  text "R" at 2263.78,2590.55 h28
  text "E" at 2362.2,2590.55 h28
Mechanical 1:
  lines w3.94: 1500,2464.57 1500,1500 2444.88,1500 ; 1500,2466.14 cw(c1539.37,2466.14) 1519.69,2500.24 ; 1519.31,2500.58 1798.64,2681.98 ; 1775.48,3515.91 1534.46,3359.39 ccw(c1554.13,3325.32) 1520.03,3305.63 1799.1,2875.91 1799.1,2681.22 ; 1775.59,3515.91 1775.59,3625.98 4106.3,3625.98 4106.3,3515.91 ; 2445.28,1500 2491.43,1626.81 ; 2491.54,1626.77 cw(c2535.01,1608.27) 2535.01,1655.51 3331.79,1655.51 ; 3331.79,1655.6 cw(c3331.79,1608.36) 3375.26,1626.86 3438.16,1456.69 ; 3438.98,1456.69 4381.89,1456.69 ; 4082.68,2681.98 4362.01,2500.58 ; 4082.79,2681.22 4082.79,2875.91 4361.86,3305.63 ccw(c4327.76,3325.32) 4347.45,3359.41 4106.41,3515.91 ; 4361.64,2500.24 cw(c4341.95,2466.14) 4381.32,2466.14 ; 4381.32,1456.69 4381.32,2464.57
Mechanical 15:
  drawing of 230 lines, arcs and shapes, not listed

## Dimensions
1500,1484.25 to 2444.88,1480.32 on Mechanical 1
1799.21,2901.57 to 4082.68,2905.51 on Mechanical 1
1500,1488.19 to 4381.89,1440.94 on Mechanical 1
4401.57,1456.69 to 4118.11,3625.98 on Mechanical 1
3438.98,1429.13 to 4381.89,1429.92 on Mechanical 1
1546.46,3320.87 to 4118.11,3625.98 on Mechanical 1
4391.73,2470.47 to 4118.11,3625.98 on Mechanical 1
1762.48,2677.17 to 1468.52,2483.98 on Mechanical 1
1480.32,1714.57 to 1480.31,3625.98 on Mechanical 1
1486.22,2488.19 to 1480.31,3625.98 on Mechanical 1
1484.25,1501.97 to 1362.2,3625.98 on Mechanical 1
1482.28,3336.61 to 1755.9,3625.98 on Mechanical 1
1500,3393.7 to 4381.89,3645.67 on Mechanical 1
1622.05,2377.95 to 4259.84,2240.16 on Mechanical 1
1775.59,3645.67 to 4106.3,3645.67 on Mechanical 1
